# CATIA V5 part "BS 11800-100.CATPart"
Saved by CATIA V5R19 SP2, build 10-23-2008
Part number: BS 11800-100
Bounding box of the stored display mesh (mm): x -74.81 to 74.81, y -74.81 to 74.81, z 0 to 278
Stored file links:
  C:\Users\Bora\Desktop\3D Katı model\BS serisi\BS 11800\BS 11800-100.CATPart
  C:\Program Files\Dassault Systemes\B19\intel_a\reffiles\standard\MetricThickPitch.txt
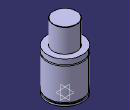
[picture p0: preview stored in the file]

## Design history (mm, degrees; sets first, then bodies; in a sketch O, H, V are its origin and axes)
Body1 (main body)
  Sketch1 on yz-plane, origin (0, 0, 0), H (0, 1, 0), V (0, 0, 1)
    point P1 (75, 155)
    point P2 (75, 150)
    point P5 (50, 277)
    point P7 (50, 277)
    point P12 (75, 150)
    point P13 (75, 155)
    arc A1 centre (75, 152.5) radius 2.5 from (75, 155) to (75, 150) ccw
    line L1 (75, 0) -> (75, 8)
    line L2 (50, 277) -> (50, 177)
    arc A2 centre (49, 277) radius 1 from (50, 277) to (49, 278) ccw
    line L3 (71, 15) -> (71, 8)
    line L4 (75, 15) -> (75, 150)
    line L5 (75, 155) -> (75, 177)
    line L6 (49, 278) -> (0, 278)
    point P15 (0, 278)
    line L7 (50, 177) -> (75, 177)
    line L8 (0, 0) -> (75, 0)
    line L9 (71, 15) -> (75, 15)
    line L10 (71, 8) -> (75, 8)
    coincidence: P15 V, P1 P13, P2 P12, P5 P7
    tangency: L6 A2
    horizontal: L7 H, L8 H, L9 H, L10 H
  Shaft1: profile Sketch1, axis Sketch1.V, angle 360
  Sketch2 on face of Shaft1 from Sketch1.L8, origin (0, 0, 0), H (1, 0, 0), V (0, -1, 0)
    point P1 (50, 0)
    distance P1 V = 50
  Hole1: placed by Sketch2, at (50, 0, 0) direction (0, 0, 1), diameter 8.376, depth 12, threaded "M10", thread diameter 10, thread depth 12, pitch 1.5
  CircPattern1: of Hole1, instances 4, angular step 90, axis from xy-plane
